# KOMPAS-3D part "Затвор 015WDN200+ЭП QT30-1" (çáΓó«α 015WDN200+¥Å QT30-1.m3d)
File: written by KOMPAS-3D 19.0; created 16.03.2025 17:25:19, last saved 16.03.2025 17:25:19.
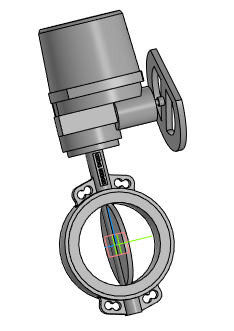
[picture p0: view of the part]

Document properties: Полное имя файла: Затвор 015WDN200+ЭП QT30-1.a3d

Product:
- Part/product: Затвор 015WDN200+ЭП QT30-1
    Масса: 98.0729

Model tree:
1. Операция без истории:1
